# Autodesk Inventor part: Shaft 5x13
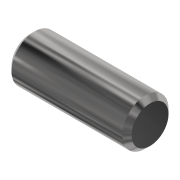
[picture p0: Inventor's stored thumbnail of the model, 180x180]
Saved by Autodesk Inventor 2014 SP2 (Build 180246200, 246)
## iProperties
Created: 2016-02
Part Number: Shaft 5x13
Material: Steel
Document SubType Name: Modeling
Designer: User
Density: 7.85 g/cm^3
Appearance: Steel - Polished
Author: User
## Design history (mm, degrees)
sketch "Sketch1"
  geometry: L1 (-6.5, 2.5)-(6.5, 2.5); L2 (6.5, 2.5)-(6.5, 0); L3 (6.5, 0)-(-6.5, 0); L4 (-6.5, 0)-(-6.5, 2.5); 2 further points
  constraints: 8 end point, 2 parallel, 1 coincident, 1 horizontal, 1 midpoint, 1 perpendicular
  dimensions: "d0" = 5 diameter of L1 L3; "d1" = 13 distance between parallel lines of L2 L4
revolve "Revolution1" sketch "Sketch1" stored, may be unused: angle "d2" = 90 deg
chamfer "Chamfer1" distance "d3" = 0.5; stored, may be unused: second distance "d4" = 2, angle "d5" = 45 deg
body "Solid1"
